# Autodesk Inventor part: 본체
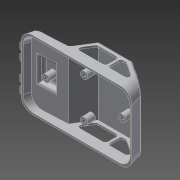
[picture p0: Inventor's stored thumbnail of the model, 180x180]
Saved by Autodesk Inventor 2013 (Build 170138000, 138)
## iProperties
Created: 2015-05
Part Number: 본체
Material: 알루미늄 6061
Document SubType Name: Modeling
Designer: WINDOWS7
Density: 2.71 g/cm^3
Author: WINDOWS7
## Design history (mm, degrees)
sketch "스케치3"
  geometry: L1 (0, 0)-(122, 0); L2 (0, 0)-(2.412, 9); L3 (2.412, 9)-(42, 11); L4 (42, 11)-(54.55, 31); L5 (54.55, 31)-(92, 31); L6 (92, 31)-(118.412, 13.392); L7 (118.412, 13.392)-(122, 0)
  constraints: 14 end point, 1 horizontal, 1 parallel
  dimensions: "d0" = 105 deg angle of L2 L1; "d1" = 105 deg angle of L7 L1; "d4" = 42 horizontal distance of L3.end L1.start; "d6" = 9 vertical distance of L1.start L2.end; "d7" = 125 deg angle of L4 L3; "d13" = 20 vertical distance of L3.end L4.end; "d17" = 31 vertical distance of L5.end L1.end; "d28" = 50 horizontal distance of L5.end L3.end; "d29" = 31.74272 distance of L5.end L6.end; "d30" = 13.3923 vertical distance of L6.end L1.end
extrude "돌출1" new body sketch "스케치3" distance "d14" = 76; taper "d15" = 0 deg
node "작업 평면1"
sketch "스케치4"
  geometry: L1 (118.412, 13.392)-(122, 0) reference; L2 (122, 0)-(0, 0) reference; L3 (0, 0)-(2.412, 9) reference; L4 (2.412, 9)-(42, 11) reference; L5 (42, 11)-(54.55, 31) reference; L6 (54.55, 31)-(92, 31) reference; L7 (92, 31)-(118.412, 13.392) reference; L8 (2.071, 0)-(3.967, 7.076); L9 (3.967, 7.076)-(43.141, 9.055); L10 (43.141, 9.055)-(55.656, 29); L11 (55.656, 29)-(91.394, 29); L12 (91.394, 29)-(116.675, 12.146); L13 (116.675, 12.146)-(119.929, 0)
  constraints: 12 end point, 6 parallel, 2 point on line
  dimensions: "d19" = 2 distance between parallel lines of L3 L8; "d20" = 2 distance between parallel lines of L4 L9; "d21" = 2 distance between parallel lines of L5 L10; "d23" = 2 distance between parallel lines of L6 L11; "d24" = 2 distance between parallel lines of L7 L12; "d25" = 2 distance between parallel lines of L1 L13
extrude "돌출2" cut sketch "스케치4" stored distance "d26" = 72; taper "d27" = 0 deg
sketch "스케치6"
  geometry: L1 (53.327, 11)-(78.903, 11); L2 (92, 31)-(54.55, 31) reference; L3 (58.974, 26)-(78.903, 26); L4 (81.903, 23)-(81.903, 14); L5 (118.412, 13.392)-(122, 0) reference; L6 (122, 0)-(0, 0) reference; L7 (0, 0)-(2.412, 9) reference; L8 (2.412, 9)-(42, 11) reference; L9 (42, 11)-(54.55, 31) reference; L10 (54.55, 31)-(92, 31) reference; L11 (92, 31)-(118.412, 13.392) reference; L12 (50.786, 15.595)-(56.433, 24.595); L13 (86.855, 11)-(103.078, 11); L14 (83.855, 14)-(83.855, 23); L15 (86.855, 26)-(89.578, 26); L16 (91.242, 25.496)-(104.742, 16.496); A1 r 3 centre (103.078, 14) between (103.078, 11) and (104.742, 16.496); A2 r 3 centre (86.855, 23) between (86.855, 26) and (83.855, 23); A3 r 3 centre (78.903, 23) between (81.903, 23) and (78.903, 26); A4 r 3 centre (78.903, 14) between (78.903, 11) and (81.903, 14); A5 r 3 centre (86.855, 14) between (83.855, 14) and (86.855, 11); A6 r 3 centre (53.327, 14) between (50.786, 15.595) and (53.327, 11); A7 r 3 centre (58.974, 23) between (58.974, 26) and (56.433, 24.595); A8 r 3 centre (89.578, 23) between (91.242, 25.496) and (89.578, 26); 2 further points
  constraints: 16 end point, 16 point on circle, 16 tangent, 8 centre point, 7 equal radius, 4 parallel, 4 point on line, 3 perpendicular, 1 horizontal
  dimensions: "d31" = 20 distance between parallel lines of L1 L2; "d32" = 15 distance between parallel lines of L1 L3; "d33" = 34 distance of point (47.903, 11) point (81.903, 11); "d35" = 5 distance between parallel lines of L9 L12; "d36" = 5 distance between parallel lines of L11 L16; "d37" = 3 radius of A1
extrude "돌출3" cut sketch "스케치6" distance "d38" = 2; taper "d39" = 0 deg
fillet "모깎기3" dims "d48" = 12
fillet "모깎기4" dims "d49" = 12
fillet "모깎기5" dims "d50" = 3
fillet "모깎기6" dims "d51" = 3
fillet "모깎기7" dims "d52" = 3
fillet "모깎기8" dims "d53" = 3
fillet "모깎기9" dims "d54" = 3
node "작업 평면2"
sketch "스케치8"
  geometry: L1 (26, 0)-(26, 55.115); L2 (64, 10.039)-(64, 16.87) reference; A1 r 4 centre (5, 0) between (9, 0) and (1, 0); A2 r 4 centre (16, 0) between (20, 0) and (12, 0); A3 r 4 centre (36, 0) between (40, 0) and (32, 0); A4 r 4 centre (47, 0) between (51, 0) and (43, 0); 3 further points
  constraints: 8 point on circle, 4 centre point, 2 end point, 1 vertical, 14 other
  dimensions: "d56" = 38 distance between parallel lines of L2 L1; "d57" = 8 diameter of A1; "d58" = 8 diameter of A2; "d59" = 8 diameter of A3; "d60" = 8 diameter of A4; "d61" = 11 distance of A2.centre A1.centre; "d62" = 11 distance of A4.centre A3.centre; "d63" = 10 distance from line of L1 A3.centre; "d64" = 10 distance from line of L1 A2.centre
extrude "돌출5" join sketch "스케치8" stored distance "d65" = 5; taper "d66" = 0 deg
chamfer "모따기1" distance "d67" = 1; stored, may be unused: second distance "d68" = 2, angle "d69" = 45 deg
chamfer "모따기2" distance "d70" = 1; stored, may be unused: second distance "d71" = 2, angle "d72" = 45 deg
chamfer "모따기3" distance "d73" = 1; stored, may be unused: second distance "d74" = 2, angle "d75" = 45 deg
chamfer "모따기4" distance "d76" = 1; stored, may be unused: second distance "d77" = 2, angle "d78" = 45 deg
sketch "스케치10"
  geometry: L1 (-31.135, 74)-(65.894, 74) reference; L2 (-30.543, 49)-(-12.543, 49); L3 (-12.543, 49)-(-12.543, 25); L4 (-12.543, 25)-(-30.543, 25); L5 (-30.543, 25)-(-30.543, 49); L6 (-30.543, 49)-(-12.543, 25); L7 (-12.543, 49)-(-30.543, 25); L8 (-43.543, 42)-(-43.543, 30) reference; 2 further points
  constraints: 12 end point, 2 midpoint, 2 parallel, 1 horizontal, 1 perpendicular
  dimensions: "d80" = 18 distance of L2.start L2.end; "d81" = 24 distance of L4.end L2.start; "d82" = 13 distance between parallel lines of L5 L8
sketch "스케치11"
  geometry: L1 (31.692, 64)-(9.457, 64) reference; L2 (5.953, 39)-(25.953, 39); L3 (25.953, 39)-(25.953, 13); L4 (25.953, 13)-(5.953, 13); L5 (5.953, 13)-(5.953, 39); L6 (5.953, 39)-(25.953, 13); L7 (25.953, 39)-(5.953, 13); L8 (-5.047, 20)-(-5.047, 32) reference; 2 further points
  constraints: 12 end point, 2 midpoint, 2 parallel, 1 horizontal, 1 perpendicular
  dimensions: "d84" = 20 distance of L2.start L2.end; "d85" = 26 distance of L4.end L2.start; "d86" = 11 distance between parallel lines of L5 L8
extrude "돌출6" join sketch "스케치11" distance "d87" = 5; taper "d88" = 0 deg
fillet "모깎기10" dims "d89" = 3
extrude "돌출7" cut sketch "스케치10" distance "d90" = 5; taper "d91" = 0 deg
fillet "모깎기11" dims "d92" = 3
fillet "모깎기12" dims "d93" = 3
fillet "모깎기13" dims "d94" = 3
sketch "스케치12"
  geometry: L1 (-29.543, 48.912)-(-27.627, 48.912) reference; L2 (-27.627, 48.912)-(-27.627, 27.916) reference; L3 (-27.627, 27.916)-(-12.63, 27.916) reference; L4 (-12.63, 46)-(-12.63, 27.916) reference; L5 (-27.627, 48.912)-(-15.543, 48.912) reference; L6 (-32.455, 26)-(-32.455, 46) reference; L7 (-15.543, 23.088)-(-29.543, 23.088) reference; L8 (-12.63, 27.916)-(-12.63, 26) reference; L9 (41.019, 72)-(39.064, 72) reference; L10 (39.064, 72)-(39.064, 74) reference; L11 (39.064, 74)-(41.019, 74) reference; L12 (41.019, 74)-(41.019, 72) reference; L13 (66.02, 1.479)-(66.02, 70.521) reference; L14 (60.987, 71.97)-(60.987, 74) reference; L15 (60.987, 74)-(62.163, 74) reference; L16 (69.376, 69.613)-(69.376, 2.387) reference; L17 (62.163, -2)-(60.987, -2) reference; L18 (60.987, -2)-(60.987, 0.03) reference; L19 (3.501, 0)-(7.479, 0) reference; L20 (7.479, 0)-(7.479, -2) reference; L21 (7.479, -2)-(4.722, -2) reference; L22 (1.059, 1)-(1.059, 71) reference; L23 (4.722, 74)-(7.479, 74) reference; L24 (7.479, 74)-(7.479, 72) reference; L25 (7.479, 72)-(3.501, 72) reference; L26 (3.501, 72)-(3.501, 0) reference; L27 (39.064, 0)-(41.019, 0) reference; L28 (41.019, 0)-(41.019, -2) reference; L29 (41.019, -2)-(39.064, -2) reference; L30 (39.064, -2)-(39.064, 0) reference; L31 (-31.135, 74)-(65.894, 74) reference; C1 r 4 at (-20.128, 36); C2 r 4 at (19.872, 14); C3 r 4 at (19.872, 58); C4 r 4 at (59.872, 36); 9 further points; 6 other entities
  constraints: 4 centre point, 12 other
  dimensions: "d95" = 8 diameter of C1; "d99" = 8 diameter of C2; "d100" = 8 diameter of C4; "d101" = 40 horizontal distance of C2.centre C4.centre; "d102" = 40 horizontal distance of C2.centre C1.centre; "d105" = 8 diameter of C3
extrude "돌출8" join sketch "스케치12" distance "d103" = 9; taper "d104" = 0 deg
sketch "스케치13"
  geometry: L1 (84.222, -38)-(-9.879, -38) reference; L2 (-22.489, -26)-(-22.489, -23.631) reference; L3 (-24.59, -22.843)-(-24.59, -19.157) reference; L4 (-22.489, -18.369)-(-22.489, -12.631) reference; L5 (-24.59, -11.843)-(-24.59, -8.157) reference; L6 (-22.489, -7.369)-(-22.489, 7.369) reference; L7 (-24.59, 8.157)-(-24.59, 11.843) reference; L8 (-22.489, 12.631)-(-22.489, 18.369) reference; L9 (-24.59, 19.157)-(-24.59, 22.843) reference; L10 (-22.489, 23.631)-(-22.489, 26) reference; L11 (-9.879, 38)-(84.222, 38) reference; L12 (96.495, 26)-(96.495, -26) reference; L13 (94.449, -24)-(94.449, 24) reference; L14 (82.176, 36)-(-7.777, 36) reference; L15 (-20.387, 24)-(-20.387, -24) reference; L16 (-7.777, -36)-(82.176, -36) reference; C1 r 4 at (0, 0) reference; C2 r 4 at (40, 22) reference; C3 r 4 at (40, -22) reference; C4 r 4 at (80, 0) reference; 29 further points; 16 other entities
  constraints: 4 coincident, 24 other
hole "구멍1" sketch "스케치13" at (0, 0), (40, 22), (80, 0), (40, -22) diameter "d106" = 3.242; stored, may be unused: countersink angle "d110" = 90 deg, drill point angle "d112" = 118 deg; dims "d107" = 9, "d108" = 4, "d109" = 2, "d111" = 10
node "작업 평면4"
  node "작업 평면3"
sketch "스케치14"
  geometry: 1 further point
sketch "스케치15"
  geometry: L1 (65.791, 9)-(65.791, 61) reference; 2 further points
  constraints: 1 other
  dimensions: "d114" = 50 distance from line of point (15.791, 37.84) L1
feature "엠보싱1" sketch "스케치15" dims "d0" = 105 deg, "d1" = 105 deg, "d4" = 42, "d6" = 9, "d7" = 125 deg, "d13" = 20, "d17" = 31, "d28" = 50, "d29" = 31.74272, "d30" = 13.3923, "d115" = 0.5, "d116" = 0
node "솔리드1"
mirror "대칭1"
node "절단 모서리 투영1"
node "절단 모서리 투영2"
node "절단 모서리 투영3"
node "절단 모서리 투영4"
other parameters: "d18" = -38, "d55" = 2, "d113" = 22
